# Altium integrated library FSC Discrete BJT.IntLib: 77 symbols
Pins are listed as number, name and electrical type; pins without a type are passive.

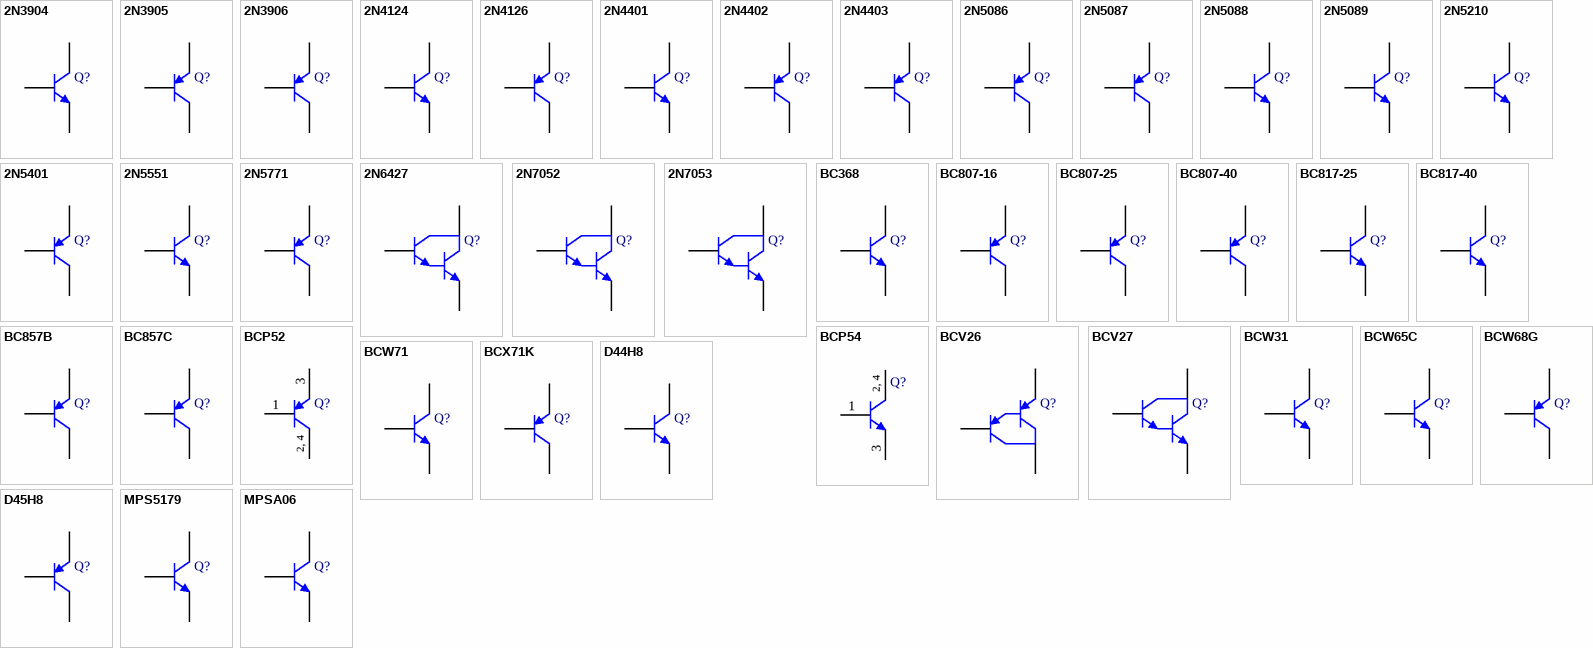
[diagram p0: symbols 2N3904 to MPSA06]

## 2N3904
designator Q?
NPN General Purpose Amplifier
footprint TO-92A (TO, Flat Index; 3 In-Line, Axial Leads; Body Dia. 4.5mm; Leads 0.51 x 0.48 mm (max))
simulation model 2N3904 (NPN)
signal-integrity model 2N3904
pins: 1 E, 2 B, 3 C

## 2N3905
designator Q?
PNP General Purpose Amplifier
footprint TO-92A (TO, Flat Index; 3 In-Line, Axial Leads; Body Dia. 4.5mm; Leads 0.51 x 0.48 mm (max))
simulation model 2N3905 (PNP)
signal-integrity model 2N3905
pins: 1 E, 2 B, 3 C

## 2N3906
designator Q?
PNP General Purpose Amplifier
footprint TO-92A (TO, Flat Index; 3 In-Line, Axial Leads; Body Dia. 4.5mm; Leads 0.51 x 0.48 mm (max))
simulation model 2N3906 (PNP)
signal-integrity model 2N3906
pins: 1 E, 2 B, 3 C

## 2N4124
designator Q?
NPN General Purpose Amplifier
footprint TO-92A (TO, Flat Index; 3 In-Line, Axial Leads; Body Dia. 4.5mm; Leads 0.51 x 0.48 mm (max))
simulation model 2N4124 (NPN)
signal-integrity model 2N4124
pins: 1 E, 2 B, 3 C

## 2N4126
designator Q?
PNP General Purpose Amplifier
footprint TO-92A (TO, Flat Index; 3 In-Line, Axial Leads; Body Dia. 4.5mm; Leads 0.51 x 0.48 mm (max))
simulation model 2N4126 (PNP)
signal-integrity model 2N4126
pins: 1 E, 2 B, 3 C

## 2N4401
designator Q?
NPN General Purpose Amplifier
footprint TO-92A (TO, Flat Index; 3 In-Line, Axial Leads; Body Dia. 4.5mm; Leads 0.51 x 0.48 mm (max))
simulation model 2N4401 (NPN)
signal-integrity model 2N4401
pins: 1 E, 2 B, 3 C

## 2N4402
designator Q?
PNP General Purpose Amplifier
footprint TO-92A (TO, Flat Index; 3 In-Line, Axial Leads; Body Dia. 4.5mm; Leads 0.51 x 0.48 mm (max))
simulation model 2N4402 (PNP)
signal-integrity model 2N4402
pins: 1 E, 2 B, 3 C

## 2N4403
designator Q?
PNP General Purpose Amplifier
footprint TO-92A (TO, Flat Index; 3 In-Line, Axial Leads; Body Dia. 4.5mm; Leads 0.51 x 0.48 mm (max))
simulation model 2N4403 (PNP)
signal-integrity model 2N4403
pins: 1 E, 2 B, 3 C

## 2N5086
designator Q?
PNP General Purpose Amplifier
footprint TO-92A (TO, Flat Index; 3 In-Line, Axial Leads; Body Dia. 4.5mm; Leads 0.51 x 0.48 mm (max))
simulation model 2N5086 (PNP)
signal-integrity model 2N5086
pins: 1 E, 2 B, 3 C

## 2N5087
designator Q?
PNP General Purpose Amplifier
footprint TO-92A (TO, Flat Index; 3 In-Line, Axial Leads; Body Dia. 4.5mm; Leads 0.51 x 0.48 mm (max))
simulation model 2N5087 (PNP)
signal-integrity model 2N5087
pins: 1 E, 2 B, 3 C

## 2N5088
designator Q?
NPN General Purpose Amplifier
footprint TO-92A (TO, Flat Index; 3 In-Line, Axial Leads; Body Dia. 4.5mm; Leads 0.51 x 0.48 mm (max))
simulation model 2N5088 (NPN)
signal-integrity model 2N5088
pins: 1 E, 2 B, 3 C

## 2N5089
designator Q?
NPN General Purpose Amplifier
footprint TO-92A (TO, Flat Index; 3 In-Line, Axial Leads; Body Dia. 4.5mm; Leads 0.51 x 0.48 mm (max))
simulation model 2N5089 (NPN)
signal-integrity model 2N5089
pins: 1 E, 2 B, 3 C

## 2N5210
designator Q?
NPN General Purpose Amplifier
footprint TO-92A (TO, Flat Index; 3 In-Line, Axial Leads; Body Dia. 4.5mm; Leads 0.51 x 0.48 mm (max))
simulation model 2N5210 (NPN)
signal-integrity model 2N5210
pins: 1 E, 2 B, 3 C

## 2N5401
designator Q?
PNP General Purpose Amplifier
footprint TO-92A (TO, Flat Index; 3 In-Line, Axial Leads; Body Dia. 4.5mm; Leads 0.51 x 0.48 mm (max))
simulation model 2N5401 (PNP)
signal-integrity model 2N5401
pins: 1 E, 2 B, 3 C

## 2N5551
designator Q?
NPN General Purpose Amplifier
footprint TO-92A (TO, Flat Index; 3 In-Line, Axial Leads; Body Dia. 4.5mm; Leads 0.51 x 0.48 mm (max))
simulation model 2N5551 (NPN)
signal-integrity model 2N5551
pins: 1 E, 2 B, 3 C

## 2N5771
designator Q?
PNP Switching Transistor
footprint TO-92A (TO, Flat Index; 3 In-Line, Axial Leads; Body Dia. 4.5mm; Leads 0.51 x 0.48 mm (max))
simulation model 2N5771 (PNP)
signal-integrity model 2N5771
pins: 1 E, 2 B, 3 C

## 2N6427
designator Q?
NPN Darlington Transistor
footprint TO-92A (TO, Flat Index; 3 In-Line, Axial Leads; Body Dia. 4.5mm; Leads 0.51 x 0.48 mm (max))
simulation model 2N6427 (SUBCKT)
pins: 1 E, 2 B, 3 C

## 2N7052
designator Q?
NPN Darlington Transistor
footprint TO-92A (TO, Flat Index; 3 In-Line, Axial Leads; Body Dia. 4.5mm; Leads 0.51 x 0.48 mm (max))
simulation model 2N7052 (SUBCKT)
pins: 1 E, 2 B, 3 C

## 2N7053
designator Q?
NPN Darlington Transistor
footprint TO-226AE (TO, Flat Index; 3 In-Line, Axial Leads; Body Dia. 4.5mm; Leads 0.51 x 0.48 mm (max))
simulation model 2N7053 (SUBCKT)
pins: 1 E, 2 B, 3 C

## BC368
designator Q?
NPN General Purpose Amplifier
footprint TO-92A (TO, Flat Index; 3 In-Line, Axial Leads; Body Dia. 4.5mm; Leads 0.51 x 0.48 mm (max))
simulation model BC368 (NPN)
signal-integrity model BC368
pins: 1 E, 2 C, 3 B

## BC807-16
designator Q?
PNP General Purpose Amplifier
footprint SOT-23A_N (SOT23, 3-Leads, Body 2.9x1.3mm, Pitch 0.95mm, Lead Span 2.3mm, IPC Medium Density)
footprint SOT-23A_L (SOT23, 3-Leads, Body 2.9x1.3mm, Pitch 0.95mm, Lead Span 2.3mm, IPC High Density)
footprint SOT-23A_M (SOT23, 3-Leads, Body 2.9x1.3mm, Pitch 0.95mm, Lead Span 2.3mm, IPC Low Density)
simulation model BC807-16 (PNP)
signal-integrity model BC807-16
pins: 1 B, 2 E, 3 C

## BC807-25
designator Q?
PNP General Purpose Amplifier
footprint SOT-23A_N (SOT23, 3-Leads, Body 2.9x1.3mm, Pitch 0.95mm, Lead Span 2.3mm, IPC Medium Density)
footprint SOT-23A_L (SOT23, 3-Leads, Body 2.9x1.3mm, Pitch 0.95mm, Lead Span 2.3mm, IPC High Density)
footprint SOT-23A_M (SOT23, 3-Leads, Body 2.9x1.3mm, Pitch 0.95mm, Lead Span 2.3mm, IPC Low Density)
simulation model BC807-25 (PNP)
signal-integrity model BC807-25
pins: 1 B, 2 E, 3 C

## BC807-40
designator Q?
PNP General Purpose Amplifier
footprint SOT-23A_N (SOT23, 3-Leads, Body 2.9x1.3mm, Pitch 0.95mm, Lead Span 2.3mm, IPC Medium Density)
footprint SOT-23A_L (SOT23, 3-Leads, Body 2.9x1.3mm, Pitch 0.95mm, Lead Span 2.3mm, IPC High Density)
footprint SOT-23A_M (SOT23, 3-Leads, Body 2.9x1.3mm, Pitch 0.95mm, Lead Span 2.3mm, IPC Low Density)
simulation model BC807-40 (PNP)
signal-integrity model BC807-40
pins: 1 B, 2 E, 3 C

## BC817-25
designator Q?
NPN General Purpose Amplifier
footprint SOT-23A_N (SOT23, 3-Leads, Body 2.9x1.3mm, Pitch 0.95mm, Lead Span 2.3mm, IPC Medium Density)
footprint SOT-23A_L (SOT23, 3-Leads, Body 2.9x1.3mm, Pitch 0.95mm, Lead Span 2.3mm, IPC High Density)
footprint SOT-23A_M (SOT23, 3-Leads, Body 2.9x1.3mm, Pitch 0.95mm, Lead Span 2.3mm, IPC Low Density)
simulation model BC817-25 (NPN)
signal-integrity model BC817-25
pins: 1 B, 2 E, 3 C

## BC817-40
designator Q?
NPN General Purpose Amplifier
footprint SOT-23A_N (SOT23, 3-Leads, Body 2.9x1.3mm, Pitch 0.95mm, Lead Span 2.3mm, IPC Medium Density)
footprint SOT-23A_L (SOT23, 3-Leads, Body 2.9x1.3mm, Pitch 0.95mm, Lead Span 2.3mm, IPC High Density)
footprint SOT-23A_M (SOT23, 3-Leads, Body 2.9x1.3mm, Pitch 0.95mm, Lead Span 2.3mm, IPC Low Density)
simulation model BC817-40 (NPN)
signal-integrity model BC817-40
pins: 1 B, 2 E, 3 C

## BC857B
designator Q?
PNP General Purpose Amplifier
footprint SOT-23A_N (SOT23, 3-Leads, Body 2.9x1.3mm, Pitch 0.95mm, Lead Span 2.3mm, IPC Medium Density)
footprint SOT-23A_L (SOT23, 3-Leads, Body 2.9x1.3mm, Pitch 0.95mm, Lead Span 2.3mm, IPC High Density)
footprint SOT-23A_M (SOT23, 3-Leads, Body 2.9x1.3mm, Pitch 0.95mm, Lead Span 2.3mm, IPC Low Density)
simulation model BC857B (PNP)
signal-integrity model BC857B
pins: 1 B, 2 E, 3 C

## BC857C
designator Q?
PNP General Purpose Amplifier
footprint SOT-23A_N (SOT23, 3-Leads, Body 2.9x1.3mm, Pitch 0.95mm, Lead Span 2.3mm, IPC Medium Density)
footprint SOT-23A_L (SOT23, 3-Leads, Body 2.9x1.3mm, Pitch 0.95mm, Lead Span 2.3mm, IPC High Density)
footprint SOT-23A_M (SOT23, 3-Leads, Body 2.9x1.3mm, Pitch 0.95mm, Lead Span 2.3mm, IPC Low Density)
simulation model BC857C (PNP)
signal-integrity model BC857C
pins: 1 B, 2 E, 3 C

## BCP52
designator Q?
PNP General Purpose Amplifier
footprint SOT-223B_N (SOT223, 4-Leads, Body 6.5x3.5mm, Pitch 2.3mm, Lead Span 7mm, IPC Medium Density)
footprint SOT-223B_L (SOT223, 4-Leads, Body 6.5x3.5mm, Pitch 2.3mm, Lead Span 7mm, IPC High Density)
footprint SOT-223B_M (SOT223, 4-Leads, Body 6.5x3.5mm, Pitch 2.3mm, Lead Span 7mm, IPC Low Density)
simulation model BCP52 (PNP)
signal-integrity model BCP52
pins: 1 B, 2 C, 3 E, 4 C

## BCP54
designator Q?
NPN General Purpose Amplifier
footprint SOT-223B_N (SOT223, 4-Leads, Body 6.5x3.5mm, Pitch 2.3mm, Lead Span 7mm, IPC Medium Density)
footprint SOT-223B_L (SOT223, 4-Leads, Body 6.5x3.5mm, Pitch 2.3mm, Lead Span 7mm, IPC High Density)
footprint SOT-223B_M (SOT223, 4-Leads, Body 6.5x3.5mm, Pitch 2.3mm, Lead Span 7mm, IPC Low Density)
simulation model BCP54 (NPN)
signal-integrity model BCP54
pins: 1 B, 2 C, 3 E, 4 C

## BCV26
designator Q?
PNP Darlington Transistor
footprint SOT-23A_N (SOT23, 3-Leads, Body 2.9x1.3mm, Pitch 0.95mm, Lead Span 2.3mm, IPC Medium Density)
footprint SOT-23A_L (SOT23, 3-Leads, Body 2.9x1.3mm, Pitch 0.95mm, Lead Span 2.3mm, IPC High Density)
footprint SOT-23A_M (SOT23, 3-Leads, Body 2.9x1.3mm, Pitch 0.95mm, Lead Span 2.3mm, IPC Low Density)
simulation model BCV26 (SUBCKT)
pins: 1 B, 2 E, 3 C

## BCV27
designator Q?
NPN Darlington Transistor
footprint SOT-23A_N (SOT23, 3-Leads, Body 2.9x1.3mm, Pitch 0.95mm, Lead Span 2.3mm, IPC Medium Density)
footprint SOT-23A_L (SOT23, 3-Leads, Body 2.9x1.3mm, Pitch 0.95mm, Lead Span 2.3mm, IPC High Density)
footprint SOT-23A_M (SOT23, 3-Leads, Body 2.9x1.3mm, Pitch 0.95mm, Lead Span 2.3mm, IPC Low Density)
simulation model BCV27 (SUBCKT)
pins: 1 B, 2 E, 3 C

## BCW31
designator Q?
NPN Epitaxial Silicon Transistor
footprint SOT-23A_N (SOT23, 3-Leads, Body 2.9x1.3mm, Pitch 0.95mm, Lead Span 2.3mm, IPC Medium Density)
footprint SOT-23A_L (SOT23, 3-Leads, Body 2.9x1.3mm, Pitch 0.95mm, Lead Span 2.3mm, IPC High Density)
footprint SOT-23A_M (SOT23, 3-Leads, Body 2.9x1.3mm, Pitch 0.95mm, Lead Span 2.3mm, IPC Low Density)
simulation model BCW31 (NPN)
signal-integrity model BCW31
pins: 1 B, 2 E, 3 C

## BCW65C
designator Q?
NPN General Purpose Amplifier
footprint SOT-23A_N (SOT23, 3-Leads, Body 2.9x1.3mm, Pitch 0.95mm, Lead Span 2.3mm, IPC Medium Density)
footprint SOT-23A_L (SOT23, 3-Leads, Body 2.9x1.3mm, Pitch 0.95mm, Lead Span 2.3mm, IPC High Density)
footprint SOT-23A_M (SOT23, 3-Leads, Body 2.9x1.3mm, Pitch 0.95mm, Lead Span 2.3mm, IPC Low Density)
simulation model BCW65C (NPN)
signal-integrity model BCW65C
pins: 1 B, 2 E, 3 C

## BCW68G
designator Q?
PNP General Purpose Amplifier
footprint SOT-23A_N (SOT23, 3-Leads, Body 2.9x1.3mm, Pitch 0.95mm, Lead Span 2.3mm, IPC Medium Density)
footprint SOT-23A_L (SOT23, 3-Leads, Body 2.9x1.3mm, Pitch 0.95mm, Lead Span 2.3mm, IPC High Density)
footprint SOT-23A_M (SOT23, 3-Leads, Body 2.9x1.3mm, Pitch 0.95mm, Lead Span 2.3mm, IPC Low Density)
simulation model BCW68G (PNP)
signal-integrity model BCW68G
pins: 1 B, 2 E, 3 C

## BCW71
designator Q?
NPN Epitaxial Silicon Transistor
footprint SOT-23B_N (SOT23, 3-Leads, Body 2.9x1.3mm, Pitch 0.95mm, Lead Span 2.4mm, IPC Medium Density)
footprint SOT-23B_L (SOT23, 3-Leads, Body 2.9x1.3mm, Pitch 0.95mm, Lead Span 2.4mm, IPC High Density)
footprint SOT-23B_M (SOT23, 3-Leads, Body 2.9x1.3mm, Pitch 0.95mm, Lead Span 2.4mm, IPC Low Density)
simulation model BCW71 (NPN)
signal-integrity model BCW71
pins: 1 B, 2 E, 3 C

## BCX71K
designator Q?
PNP Epitaxial Silicon Transistor
footprint SOT-23B_N (SOT23, 3-Leads, Body 2.9x1.3mm, Pitch 0.95mm, Lead Span 2.4mm, IPC Medium Density)
footprint SOT-23B_L (SOT23, 3-Leads, Body 2.9x1.3mm, Pitch 0.95mm, Lead Span 2.4mm, IPC High Density)
footprint SOT-23B_M (SOT23, 3-Leads, Body 2.9x1.3mm, Pitch 0.95mm, Lead Span 2.4mm, IPC Low Density)
simulation model BCX71K (PNP)
signal-integrity model BCX71K
pins: 1 B, 2 E, 3 C

## D44H8
designator Q?
NPN Power Amplifier
footprint TO-220 (TO, Thru-Hole, Vertical, Heatsink Mounted; 3 In-Line Leads; Pitch 2.54 mm)
simulation model D44H8 (SUBCKT)
signal-integrity model D44H8
pins: 1 B, 2 C, 3 E

## D45H8
designator Q?
PNP Power Amplifier
footprint TO-220 (TO, Thru-Hole, Vertical, Heatsink Mounted; 3 In-Line Leads; Pitch 2.54 mm)
simulation model D45H8 (SUBCKT)
signal-integrity model D45H8
pins: 1 B, 2 C, 3 E

## MPS5179
designator Q?
NPN RF Transistor
footprint TO-92A (TO, Flat Index; 3 In-Line, Axial Leads; Body Dia. 4.5mm; Leads 0.51 x 0.48 mm (max))
simulation model MPS5179_NSC (NPN)
signal-integrity model MPS5179
pins: 1 E, 2 B, 3 C

## MPSA06
designator Q?
NPN General Purpose Amplifier
footprint TO-92A (TO, Flat Index; 3 In-Line, Axial Leads; Body Dia. 4.5mm; Leads 0.51 x 0.48 mm (max))
simulation model MPSA06 (NPN)
signal-integrity model MPSA06
pins: 1 E, 2 B, 3 C

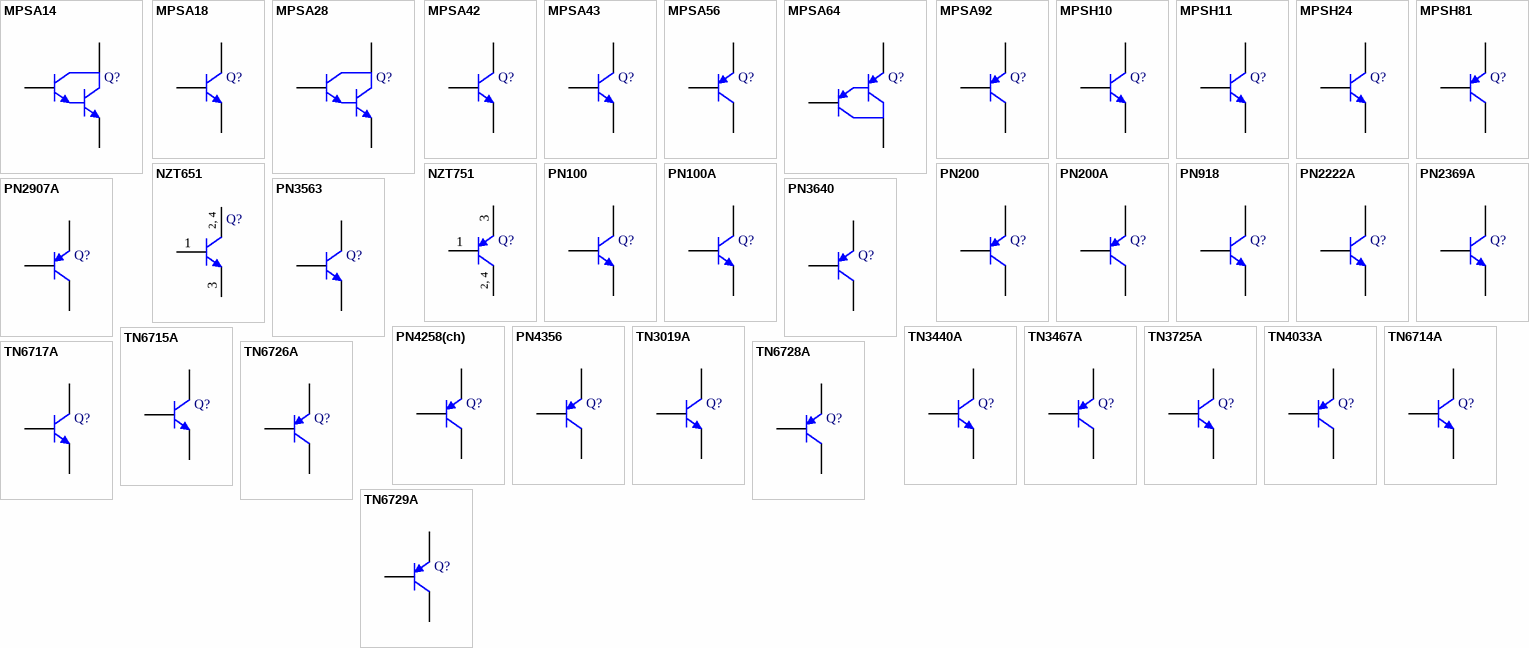
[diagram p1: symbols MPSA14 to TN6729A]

## MPSA14
designator Q?
NPN Darlington Transistor
footprint TO-92A (TO, Flat Index; 3 In-Line, Axial Leads; Body Dia. 4.5mm; Leads 0.51 x 0.48 mm (max))
simulation model MPSA14 (SUBCKT)
pins: 1 E, 2 B, 3 C

## MPSA18
designator Q?
NPN General Purpose Amplifier
footprint TO-92A (TO, Flat Index; 3 In-Line, Axial Leads; Body Dia. 4.5mm; Leads 0.51 x 0.48 mm (max))
simulation model MPSA18 (NPN)
signal-integrity model MPSA18
pins: 1 E, 2 B, 3 C

## MPSA28
designator Q?
NPN Darlington Transistor
footprint TO-92A (TO, Flat Index; 3 In-Line, Axial Leads; Body Dia. 4.5mm; Leads 0.51 x 0.48 mm (max))
simulation model MPSA28 (SUBCKT)
pins: 1 E, 2 B, 3 C

## MPSA42
designator Q?
NPN High Voltage Amplifier
footprint TO-92A (TO, Flat Index; 3 In-Line, Axial Leads; Body Dia. 4.5mm; Leads 0.51 x 0.48 mm (max))
simulation model MPSA42 (NPN)
signal-integrity model MPSA42
pins: 1 E, 2 B, 3 C

## MPSA43
designator Q?
NPN High Voltage Amplifier
footprint TO-92A (TO, Flat Index; 3 In-Line, Axial Leads; Body Dia. 4.5mm; Leads 0.51 x 0.48 mm (max))
simulation model MPSA43 (NPN)
signal-integrity model MPSA43
pins: 1 E, 2 B, 3 C

## MPSA56
designator Q?
PNP General Purpose Amplifier
footprint TO-92A (TO, Flat Index; 3 In-Line, Axial Leads; Body Dia. 4.5mm; Leads 0.51 x 0.48 mm (max))
simulation model MPSA56 (PNP)
signal-integrity model MPSA56
pins: 1 E, 2 B, 3 C

## MPSA64
designator Q?
PNP Darlington Transistor
footprint TO-92A (TO, Flat Index; 3 In-Line, Axial Leads; Body Dia. 4.5mm; Leads 0.51 x 0.48 mm (max))
simulation model MPSA64_NSC (SUBCKT)
pins: 1 E, 2 B, 3 C

## MPSA92
designator Q?
PNP High Voltage Amplifier
footprint TO-92A (TO, Flat Index; 3 In-Line, Axial Leads; Body Dia. 4.5mm; Leads 0.51 x 0.48 mm (max))
simulation model MPSA92 (PNP)
signal-integrity model MPSA92
pins: 1 E, 2 B, 3 C

## MPSH10
designator Q?
NPN RF Transistor
footprint TO-92A (TO, Flat Index; 3 In-Line, Axial Leads; Body Dia. 4.5mm; Leads 0.51 x 0.48 mm (max))
simulation model MPSH10 (NPN)
signal-integrity model MPSH10
pins: 1 B, 2 E, 3 C

## MPSH11
designator Q?
NPN RF Transistor
footprint TO-92A (TO, Flat Index; 3 In-Line, Axial Leads; Body Dia. 4.5mm; Leads 0.51 x 0.48 mm (max))
simulation model MPSH11 (NPN)
signal-integrity model MPSH11
pins: 1 E, 2 B, 3 C

## MPSH24
designator Q?
NPN RF Transistor
footprint TO-92A (TO, Flat Index; 3 In-Line, Axial Leads; Body Dia. 4.5mm; Leads 0.51 x 0.48 mm (max))
simulation model MPSH24 (NPN)
signal-integrity model MPSH24
pins: 1 E, 2 B, 3 C

## MPSH81
designator Q?
PNP RF Transistor
footprint TO-92A (TO, Flat Index; 3 In-Line, Axial Leads; Body Dia. 4.5mm; Leads 0.51 x 0.48 mm (max))
simulation model MPSH81 (PNP)
signal-integrity model MPSH81
pins: 1 B, 2 E, 3 C

## NZT651
designator Q?
NPN Current Driver Transistor
footprint SOT-223B_N (SOT223, 4-Leads, Body 6.5x3.5mm, Pitch 2.3mm, Lead Span 7mm, IPC Medium Density)
footprint SOT-223B_L (SOT223, 4-Leads, Body 6.5x3.5mm, Pitch 2.3mm, Lead Span 7mm, IPC High Density)
footprint SOT-223B_M (SOT223, 4-Leads, Body 6.5x3.5mm, Pitch 2.3mm, Lead Span 7mm, IPC Low Density)
simulation model NZT651 (SUBCKT)
signal-integrity model NZT651
pins: 1 B, 2 C, 3 E, 4 C

## NZT751
designator Q?
PNP Current Driver Transistor
footprint SOT-223B_N (SOT223, 4-Leads, Body 6.5x3.5mm, Pitch 2.3mm, Lead Span 7mm, IPC Medium Density)
footprint SOT-223B_L (SOT223, 4-Leads, Body 6.5x3.5mm, Pitch 2.3mm, Lead Span 7mm, IPC High Density)
footprint SOT-223B_M (SOT223, 4-Leads, Body 6.5x3.5mm, Pitch 2.3mm, Lead Span 7mm, IPC Low Density)
simulation model NZT751 (SUBCKT)
signal-integrity model NZT751
pins: 1 B, 2 C, 3 E, 4 C

## PN100
designator Q?
NPN General Purpose Amplifier
footprint TO-92A (TO, Flat Index; 3 In-Line, Axial Leads; Body Dia. 4.5mm; Leads 0.51 x 0.48 mm (max))
simulation model PN100 (NPN)
signal-integrity model PN100
pins: 1 E, 2 B, 3 C

## PN100A
designator Q?
NPN General Purpose Amplifier
footprint TO-92A (TO, Flat Index; 3 In-Line, Axial Leads; Body Dia. 4.5mm; Leads 0.51 x 0.48 mm (max))
simulation model PN100A (NPN)
signal-integrity model PN100A
pins: 1 E, 2 B, 3 C

## PN200
designator Q?
PNP General Purpose Amplifier
footprint TO-92A (TO, Flat Index; 3 In-Line, Axial Leads; Body Dia. 4.5mm; Leads 0.51 x 0.48 mm (max))
simulation model PN200 (PNP)
signal-integrity model PN200
pins: 1 E, 2 B, 3 C

## PN200A
designator Q?
PNP General Purpose Amplifier
footprint TO-92A (TO, Flat Index; 3 In-Line, Axial Leads; Body Dia. 4.5mm; Leads 0.51 x 0.48 mm (max))
simulation model PN200A (PNP)
signal-integrity model PN200A
pins: 1 E, 2 B, 3 C

## PN918
designator Q?
NPN RF Transistor
footprint TO-92A (TO, Flat Index; 3 In-Line, Axial Leads; Body Dia. 4.5mm; Leads 0.51 x 0.48 mm (max))
simulation model PN918 (NPN)
signal-integrity model PN918
pins: 1 E, 2 B, 3 C

## PN2222A
designator Q?
NPN General Purpose Amplifier
footprint TO-92A (TO, Flat Index; 3 In-Line, Axial Leads; Body Dia. 4.5mm; Leads 0.51 x 0.48 mm (max))
simulation model PN2222A_NSC (NPN)
signal-integrity model PN2222A
pins: 1 E, 2 B, 3 C

## PN2369A
designator Q?
NPN Switching Transistor
footprint TO-92A (TO, Flat Index; 3 In-Line, Axial Leads; Body Dia. 4.5mm; Leads 0.51 x 0.48 mm (max))
simulation model PN2369A_NSC (NPN)
signal-integrity model PN2369A
pins: 1 E, 2 B, 3 C

## PN2907A
designator Q?
PNP General Purpose Amplifier
footprint TO-92A (TO, Flat Index; 3 In-Line, Axial Leads; Body Dia. 4.5mm; Leads 0.51 x 0.48 mm (max))
simulation model PN2907A (PNP)
signal-integrity model PN2907A
pins: 1 E, 2 B, 3 C

## PN3563
designator Q?
NPN RF Amplifier
footprint TO-92A (TO, Flat Index; 3 In-Line, Axial Leads; Body Dia. 4.5mm; Leads 0.51 x 0.48 mm (max))
simulation model PN3563 (NPN)
signal-integrity model PN3563
pins: 1 E, 2 B, 3 C

## PN3640
designator Q?
PNP Switching Transistor
footprint TO-92A (TO, Flat Index; 3 In-Line, Axial Leads; Body Dia. 4.5mm; Leads 0.51 x 0.48 mm (max))
simulation model PN3640 (PNP)
signal-integrity model PN3640
pins: 1 E, 2 B, 3 C

## PN4258(ch)
designator Q?
PNP Switching Transistor
footprint TO-92A (TO, Flat Index; 3 In-Line, Axial Leads; Body Dia. 4.5mm; Leads 0.51 x 0.48 mm (max))
simulation model PN4258_NSC (PNP)
signal-integrity model PN4258(ch)
pins: 1 E, 2 B, 3 C

## PN4356
designator Q?
PNP General Purpose Amplifier
footprint TO-92A (TO, Flat Index; 3 In-Line, Axial Leads; Body Dia. 4.5mm; Leads 0.51 x 0.48 mm (max))
simulation model PN4356 (PNP)
signal-integrity model PN4356
pins: 1 E, 2 B, 3 C

## TN3019A
designator Q?
NPN General Purpose Amplifier
footprint TO-226AE (TO, Flat Index; 3 In-Line, Axial Leads; Body Dia. 4.5mm; Leads 0.51 x 0.48 mm (max))
simulation model TN3019A (NPN)
signal-integrity model TN3019A
pins: 1 E, 2 B, 3 C

## TN3440A
designator Q?
NPN General Purpose Amplifier
footprint TO-226AE (TO, Flat Index; 3 In-Line, Axial Leads; Body Dia. 4.5mm; Leads 0.51 x 0.48 mm (max))
simulation model TN3440A (NPN)
signal-integrity model TN3440A
pins: 1 E, 2 B, 3 C

## TN3467A
designator Q?
PNP Switching Transistor
footprint TO-226AE (TO, Flat Index; 3 In-Line, Axial Leads; Body Dia. 4.5mm; Leads 0.51 x 0.48 mm (max))
simulation model TN3467A (PNP)
signal-integrity model TN3467A
pins: 1 E, 2 B, 3 C

## TN3725A
designator Q?
NPN Switching Transistor
footprint TO-226AE (TO, Flat Index; 3 In-Line, Axial Leads; Body Dia. 4.5mm; Leads 0.51 x 0.48 mm (max))
simulation model TN3725A (NPN)
signal-integrity model TN3725A
pins: 1 E, 2 B, 3 C

## TN4033A
designator Q?
PNP General Purpose Amplifier
footprint TO-226AE (TO, Flat Index; 3 In-Line, Axial Leads; Body Dia. 4.5mm; Leads 0.51 x 0.48 mm (max))
simulation model TN4033A (PNP)
signal-integrity model TN4033A
pins: 1 E, 2 B, 3 C

## TN6714A
designator Q?
NPN General Purpose Amplifier
footprint TO-226AE (TO, Flat Index; 3 In-Line, Axial Leads; Body Dia. 4.5mm; Leads 0.51 x 0.48 mm (max))
simulation model TN6714A (NPN)
signal-integrity model TN6714A
pins: 1 E, 2 B, 3 C

## TN6715A
designator Q?
NPN General Purpose Amplifier
footprint TO-226AE (TO, Flat Index; 3 In-Line, Axial Leads; Body Dia. 4.5mm; Leads 0.51 x 0.48 mm (max))
simulation model TN6715A (NPN)
signal-integrity model TN6715A
pins: 1 E, 2 B, 3 C

## TN6717A
designator Q?
NPN General Purpose Amplifier
footprint TO-226AE (TO, Flat Index; 3 In-Line, Axial Leads; Body Dia. 4.5mm; Leads 0.51 x 0.48 mm (max))
simulation model TN6717A (NPN)
signal-integrity model TN6717A
pins: 1 E, 2 B, 3 C

## TN6726A
designator Q?
PNP General Purpose Amplifier
footprint TO-226AE (TO, Flat Index; 3 In-Line, Axial Leads; Body Dia. 4.5mm; Leads 0.51 x 0.48 mm (max))
simulation model TN6726A (PNP)
signal-integrity model TN6726A
pins: 1 E, 2 B, 3 C

## TN6728A
designator Q?
PNP General Purpose Amplifier
footprint TO-226AE (TO, Flat Index; 3 In-Line, Axial Leads; Body Dia. 4.5mm; Leads 0.51 x 0.48 mm (max))
simulation model TN6728A (PNP)
signal-integrity model TN6728A
pins: 1 E, 2 B, 3 C

## TN6729A
designator Q?
PNP General Purpose Amplifier
footprint TO-226AE (TO, Flat Index; 3 In-Line, Axial Leads; Body Dia. 4.5mm; Leads 0.51 x 0.48 mm (max))
simulation model TN6729A (PNP)
signal-integrity model TN6729A
pins: 1 E, 2 B, 3 C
